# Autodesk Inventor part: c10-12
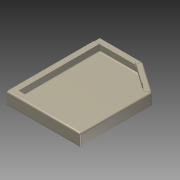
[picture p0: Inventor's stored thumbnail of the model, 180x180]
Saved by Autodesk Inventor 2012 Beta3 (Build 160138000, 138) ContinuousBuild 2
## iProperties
Created: 2011-01
Part Number: c10-12
Material: Steel, Mild
Document SubType Name: Sheet Metal
Designer: Beta-8540w
Density: 7.86 g/cm^3
Sheet Metal Rule: Steel - 16ga
Flat Pattern Width: 34.6788 cm
Flat Pattern Length: 40.6788 cm
Flat Pattern Area: 1410.69 cm^2
Sheet Metal Width: 346.788 mm
Sheet Metal Length: 406.788 mm
Sheet Metal Area: 141069.500 mm^2
Author: Beta-8540w
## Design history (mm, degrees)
node "Face1"
  sketch "Sketch1"
    geometry: L1 (0, 0)-(240, 0); L2 (240, 0)-(240, 300); L3 (240, 300)-(0, 300); L4 (0, 300)-(0, 0); L5 (140, 300)-(240, 229.979)
    constraints: 10 end point, 2 parallel, 2 point on line, 1 horizontal, 1 perpendicular
    dimensions: "d0" = 240 distance of L3.end L2.end; "d1" = 300 distance of L2.end L1.end; "d2" = 35 deg angle of L3 L5; "d3" = 100 distance from line of L2 L5.start
node "Flange1"
node "Flange2"
node "Flange3"
body "Solid1"
face "Plate1" dims "Thickness" = 1.524 (derived)
sketch "Sketch2"
  geometry: L1 (0, 40)-(-300, 40); L2 (-300, 40)-(-300, 0); 2 other entities
  constraints: 4 end point, 4 other
face "Plate2" dims "d5" = 1.524 (= BendReliefWidth), "d6" = 0.762 (= BendReliefDepth), "d7" = 3.048 (= MinimumRemnant), "d8" = 3.048 (= BendRadius), "d9" = 40, "d10" = 90 deg, "d11" = 3.048 (= BendRadius), "d12" = 6.096 (= CornerReliefSize), "d13" = 0.762 (= GapSize), "d14" = 3.048 (= JacobiRadiusSize), "SeamGap" = 0.01, "Thickness" = 1.524 (derived)
bend "Bend1" dims "d5" = 1.524 (= BendReliefWidth), "d6" = 0.762 (= BendReliefDepth), "d7" = 3.048 (= MinimumRemnant), "d8" = 3.048 (= BendRadius), "d9" = 40, "d10" = 90 deg, "d11" = 3.048 (= BendRadius), "SeamGap" = 0.01, "Thickness" = 1.524 (derived)
feature "Corner1" dims "d9" = 40, "d10" = 90 deg, "d12" = 6.096 (= CornerReliefSize), "d13" = 0.762 (= GapSize), "d14" = 3.048 (= JacobiRadiusSize)
sketch "Sketch3"
  geometry: L1 (0, 20)-(-235.874, 20); L2 (-235.874, 20)-(-235.874, 0); 2 other entities
  constraints: 4 end point, 4 other
face "Plate3" dims "d15" = 1.524 (= BendReliefWidth), "d16" = 0.762 (= BendReliefDepth), "d17" = 3.048 (= MinimumRemnant), "d18" = 3.048 (= BendRadius), "d19" = 20, "d20" = 90 deg, "d21" = 3.048 (= BendRadius), "d22" = 6.096 (= CornerReliefSize), "d23" = 0.762 (= GapSize), "d24" = 3.048 (= JacobiRadiusSize), "d26" = 10, "SeamGap" = 0.01, "Thickness" = 1.524 (derived)
bend "Bend2" dims "d15" = 1.524 (= BendReliefWidth), "d16" = 0.762 (= BendReliefDepth), "d17" = 3.048 (= MinimumRemnant), "d18" = 3.048 (= BendRadius), "d19" = 20, "d20" = 90 deg, "d21" = 3.048 (= BendRadius), "SeamGap" = 0.01, "Thickness" = 1.524 (derived)
feature "Corner2" dims "d19" = 20, "d20" = 90 deg, "d22" = 6.096 (= CornerReliefSize), "d23" = 0.762 (= GapSize), "d24" = 3.048 (= JacobiRadiusSize)
sketch "Sketch4"
  geometry: L1 (-94.531, 0)-(-10, 0); L2 (-10, 0)-(-10, 15); L3 (-10, 15)-(-94.531, 15); L4 (-94.531, 15)-(-94.531, 0)
  constraints: 8 end point
face "Plate4" dims "d27" = 1.524 (= BendReliefWidth), "d28" = 0.762 (= BendReliefDepth), "d29" = 3.048 (= MinimumRemnant), "d30" = 3.048 (= BendRadius), "d31" = 10, "d32" = 10, "d33" = 15, "d34" = 90 deg, "d35" = 3.048 (= BendRadius), "d36" = 6.096 (= CornerReliefSize), "d37" = 0.762 (= GapSize), "d38" = 3.048 (= JacobiRadiusSize), "SeamGap" = 0.01, "Thickness" = 1.524 (derived)
bend "Bend3" dims "d27" = 1.524 (= BendReliefWidth), "d28" = 0.762 (= BendReliefDepth), "d29" = 3.048 (= MinimumRemnant), "d30" = 3.048 (= BendRadius), "d33" = 15, "d34" = 90 deg, "d35" = 3.048 (= BendRadius), "SeamGap" = 0.01, "Thickness" = 1.524 (derived)
feature "Corner3" dims "d33" = 15, "d34" = 90 deg, "d36" = 6.096 (= CornerReliefSize), "d37" = 0.762 (= GapSize), "d38" = 3.048 (= JacobiRadiusSize)
feature "Definition1"
fillet "Fillet1" dims "d0" = 5
fillet "Fillet2" dims "d1" = 5
fillet "Fillet3" dims "d2" = 5
fillet "Fillet4" dims "d3" = 2
fillet "Fillet5" dims "d4" = 2
other parameters: "BendRadius" = 3.048 (= 2 x Thickness), "BendReliefWidth" = 1.524 (= Thickness), "BendReliefDepth" = 0.762 (= 0.5 x Thickness), "CornerReliefSize" = 6.096 (= 4 x Thickness), "MinimumRemnant" = 3.048 (= 2 x Thickness), "TransitionRadius" = 3.048 (= BendRadius), "JacobiRadiusSize" = 3.048 (= BendRadius), "GapSize" = 0.762 (= 0.5 x Thickness), "d4" = 3.048 (= BendRadius), "BendRadius" = 3.048, "BendReliefDepth" = 0.762, "BendReliefWidth" = 1.524, "CornerReliefSize" = 6.096, "GapSize" = 0.762, "JacobiRadiusSize" = 3.048, "MinimumRemnant" = 3.048, "Thickness" = 1.524, "TransitionRadius" = 3.048
